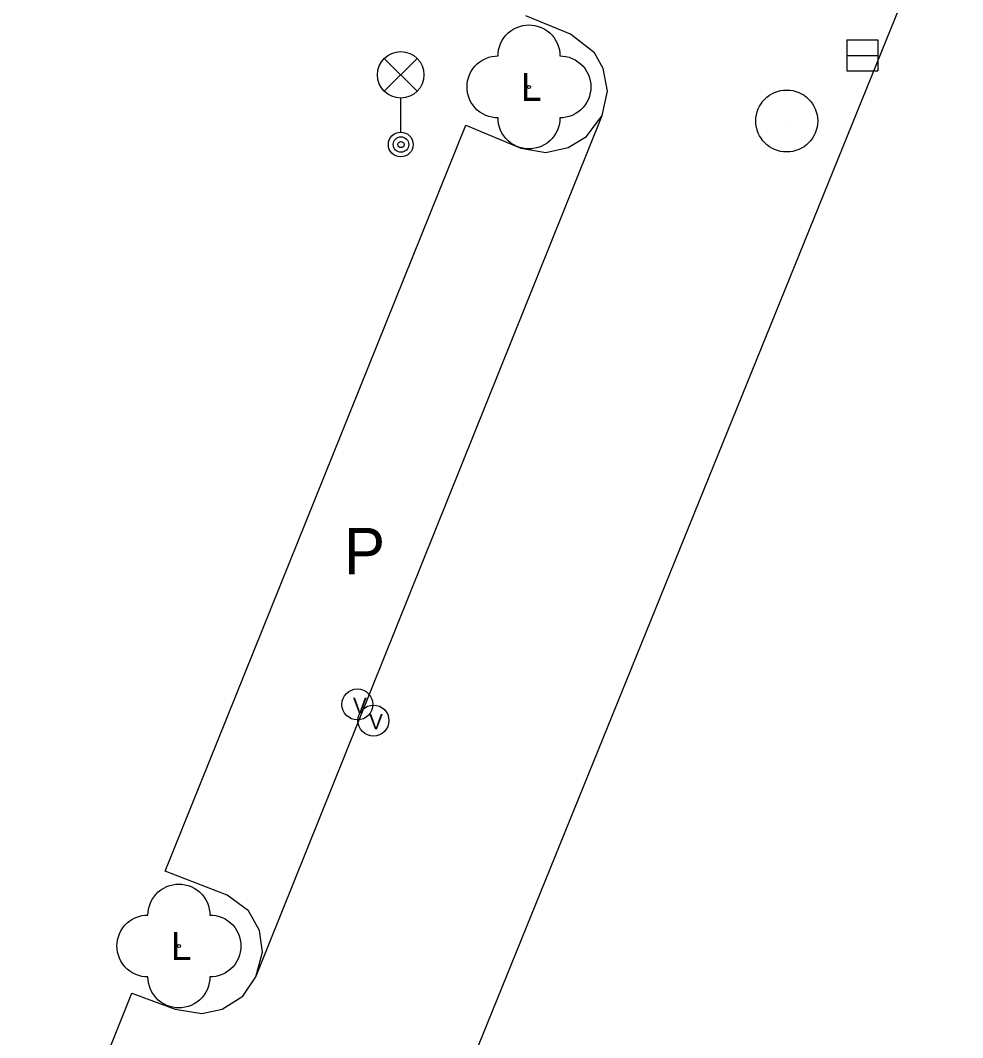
# Model space of a CAD drawing. Extents: x -836568 to -836015, y -1070547 to -1070212.
# Drawn here: x -836346.87 to -836331.66, y -1070399.69 to -1070383.27 of the extents above; entities that cross this region are included whole.
import ezdxf

# ---------------------------------------------------------------- set-up
doc = ezdxf.new("R2010")
doc.units = 0
for name, color, linetype in [('BodPole_mer', 7, 'Continuous'), ('Doprava_hranice', 7, 'Continuous'), ('Doprava_kody', 7, 'Continuous'), ('PovrZnIS_body', 7, 'Continuous'), ('Zelen_body', 7, 'Continuous')]:
    doc.layers.add(name, color=color, linetype=linetype)

msp = doc.modelspace()

# ---------------------------------------------------------------- linework, layer by layer
at = {"layer": 'BodPole_mer'}
for p, q in [((-836337.99, -1070383.49), (-836337.99, -1070383.49)), ((-836337.6, -1070383.79), (-836337.6, -1070383.79)), ((-836333.28, -1070383.83), (-836333.28, -1070383.83)), ((-836337.46, -1070384.04), (-836337.46, -1070384.04)), ((-836338.66, -1070384.34), (-836338.66, -1070384.34)), ((-836337.39, -1070384.41), (-836337.39, -1070384.41)), ((-836337.48, -1070384.8), (-836337.48, -1070384.8)), ((-836334.5, -1070384.89), (-836334.5, -1070384.89)), ((-836339.68, -1070384.96), (-836339.68, -1070384.96)), ((-836337.73, -1070385.14), (-836337.73, -1070385.14)), ((-836340.73, -1070385.27), (-836340.73, -1070385.27)), ((-836338.79, -1070385.33), (-836338.79, -1070385.33)), ((-836338.39, -1070385.4), (-836338.39, -1070385.4)), ((-836338.03, -1070385.32), (-836338.03, -1070385.32)), ((-836341.43, -1070394.31), (-836341.43, -1070394.31)), ((-836341.17, -1070394.57), (-836341.17, -1070394.57)), ((-836344.53, -1070397), (-836344.53, -1070397)), ((-836343.53, -1070397.39), (-836343.53, -1070397.39)), ((-836343.19, -1070397.64), (-836343.19, -1070397.64)), ((-836343.01, -1070397.96), (-836343.01, -1070397.96)), ((-836344.31, -1070398.21), (-836344.31, -1070398.21)), ((-836342.96, -1070398.31), (-836342.96, -1070398.31)), ((-836343.07, -1070398.71), (-836343.07, -1070398.71)), ((-836345.07, -1070398.97), (-836345.07, -1070398.97)), ((-836343.28, -1070399.02), (-836343.28, -1070399.02)), ((-836344.37, -1070399.23), (-836344.37, -1070399.23)), ((-836343.94, -1070399.3), (-836343.94, -1070399.3)), ((-836343.61, -1070399.23), (-836343.61, -1070399.23))]:
    msp.add_line(p, q, dxfattribs=at)
at = {"layer": 'Doprava_hranice'}
msp.add_line((-836343.07, -1070398.71), (-836337.48, -1070384.8), dxfattribs=at)
for points in [[(-836331.66, -1070380.54), (-836339.56, -1070400.02), (-836341.79, -1070405.5), (-836342.16, -1070406.47), (-836342.54, -1070407.49), (-836342.75, -1070408.5), (-836342.67, -1070409.47), (-836342.18, -1070410.44), (-836341.51, -1070411.06), (-836340.95, -1070411.41)], [(-836346.87, -1070403.46), (-836345.07, -1070398.97), (-836344.37, -1070399.23), (-836343.94, -1070399.3), (-836343.61, -1070399.23), (-836343.28, -1070399.02), (-836343.07, -1070398.71), (-836342.96, -1070398.31), (-836343.01, -1070397.96), (-836343.19, -1070397.64), (-836343.53, -1070397.39), (-836344.53, -1070397), (-836339.68, -1070384.96), (-836338.79, -1070385.33), (-836338.39, -1070385.4), (-836338.03, -1070385.32), (-836337.73, -1070385.14), (-836337.48, -1070384.8), (-836337.39, -1070384.41), (-836337.46, -1070384.04), (-836337.6, -1070383.79), (-836337.99, -1070383.49), (-836338.71, -1070383.19)]]:
    msp.add_lwpolyline(points, dxfattribs=at)
at = {"layer": 'PovrZnIS_body'}
for p, q in [((-836333.53, -1070383.58), (-836333.03, -1070383.58)), ((-836333.53, -1070383.58), (-836333.53, -1070384.08)), ((-836333.03, -1070383.58), (-836333.03, -1070384.08)), ((-836340.995, -1070384.41), (-836340.465, -1070383.88)), ((-836340.995, -1070383.88), (-836340.465, -1070384.41)), ((-836333.53, -1070383.83), (-836333.03, -1070383.83)), ((-836333.53, -1070384.08), (-836333.03, -1070384.08)), ((-836340.73, -1070385.07), (-836340.73, -1070384.52))]:
    msp.add_line(p, q, dxfattribs=at)
for centre, radius in [((-836334.5, -1070384.89), 0.5), ((-836341.43, -1070394.31), 0.25), ((-836341.17, -1070394.57), 0.25)]:
    msp.add_circle(centre, radius, dxfattribs=at)
for centre, major_axis in [((-836340.73, -1070384.145), (0.375, 0)), ((-836340.73, -1070385.27), (0.2, 0)), ((-836340.726, -1070385.27), (0.125, 0)), ((-836340.726, -1070385.27), (0.05, 0))]:
    msp.add_ellipse(centre, major_axis=major_axis, ratio=0.999998, dxfattribs=at)
at = {"layer": 'Zelen_body'}
for p, q in [((-836338.66, -1070384.34), (-836338.66, -1070384.34)), ((-836344.31, -1070398.21), (-836344.31, -1070398.21))]:
    msp.add_line(p, q, dxfattribs=at)
for points in [[(-836339.16, -1070383.84), (-836339.158, -1070383.792), (-836339.15, -1070383.743), (-836339.138, -1070383.693), (-836339.12, -1070383.644), (-836339.096, -1070383.595), (-836339.067, -1070383.549), (-836339.033, -1070383.506), (-836338.994, -1070383.467), (-836338.951, -1070383.433), (-836338.905, -1070383.404), (-836338.856, -1070383.38), (-836338.807, -1070383.362), (-836338.757, -1070383.35), (-836338.708, -1070383.342), (-836338.66, -1070383.34), (-836338.612, -1070383.342), (-836338.563, -1070383.35), (-836338.513, -1070383.362), (-836338.464, -1070383.38), (-836338.415, -1070383.404), (-836338.369, -1070383.433), (-836338.326, -1070383.467), (-836338.287, -1070383.506), (-836338.253, -1070383.549), (-836338.224, -1070383.595), (-836338.2, -1070383.644), (-836338.182, -1070383.693), (-836338.17, -1070383.743), (-836338.162, -1070383.792), (-836338.16, -1070383.84)], [(-836339.16, -1070384.84), (-836339.208, -1070384.838), (-836339.257, -1070384.83), (-836339.307, -1070384.818), (-836339.356, -1070384.8), (-836339.405, -1070384.776), (-836339.451, -1070384.747), (-836339.494, -1070384.713), (-836339.533, -1070384.674), (-836339.567, -1070384.631), (-836339.596, -1070384.585), (-836339.62, -1070384.536), (-836339.638, -1070384.487), (-836339.65, -1070384.437), (-836339.658, -1070384.388), (-836339.66, -1070384.34), (-836339.658, -1070384.292), (-836339.65, -1070384.243), (-836339.638, -1070384.193), (-836339.62, -1070384.144), (-836339.596, -1070384.095), (-836339.567, -1070384.049), (-836339.533, -1070384.006), (-836339.494, -1070383.967), (-836339.451, -1070383.933), (-836339.405, -1070383.904), (-836339.356, -1070383.88), (-836339.307, -1070383.862), (-836339.257, -1070383.85), (-836339.208, -1070383.842), (-836339.16, -1070383.84)], [(-836338.16, -1070383.84), (-836338.112, -1070383.842), (-836338.063, -1070383.85), (-836338.013, -1070383.862), (-836337.964, -1070383.88), (-836337.915, -1070383.904), (-836337.869, -1070383.933), (-836337.826, -1070383.967), (-836337.787, -1070384.006), (-836337.753, -1070384.049), (-836337.724, -1070384.095), (-836337.7, -1070384.144), (-836337.682, -1070384.193), (-836337.67, -1070384.243), (-836337.662, -1070384.292), (-836337.66, -1070384.34), (-836337.662, -1070384.388), (-836337.67, -1070384.437), (-836337.682, -1070384.487), (-836337.7, -1070384.536), (-836337.724, -1070384.585), (-836337.753, -1070384.631), (-836337.787, -1070384.674), (-836337.826, -1070384.713), (-836337.869, -1070384.747), (-836337.915, -1070384.776), (-836337.964, -1070384.8), (-836338.013, -1070384.818), (-836338.063, -1070384.83), (-836338.112, -1070384.838), (-836338.16, -1070384.84)], [(-836338.16, -1070384.84), (-836338.162, -1070384.888), (-836338.17, -1070384.937), (-836338.182, -1070384.987), (-836338.2, -1070385.036), (-836338.224, -1070385.085), (-836338.253, -1070385.131), (-836338.287, -1070385.174), (-836338.326, -1070385.213), (-836338.369, -1070385.247), (-836338.415, -1070385.276), (-836338.464, -1070385.3), (-836338.513, -1070385.318), (-836338.563, -1070385.33), (-836338.612, -1070385.338), (-836338.66, -1070385.34), (-836338.708, -1070385.338), (-836338.757, -1070385.33), (-836338.807, -1070385.318), (-836338.856, -1070385.3), (-836338.905, -1070385.276), (-836338.951, -1070385.247), (-836338.994, -1070385.213), (-836339.033, -1070385.174), (-836339.067, -1070385.131), (-836339.096, -1070385.085), (-836339.12, -1070385.036), (-836339.138, -1070384.987), (-836339.15, -1070384.937), (-836339.158, -1070384.888), (-836339.16, -1070384.84)], [(-836344.81, -1070397.71), (-836344.808, -1070397.662), (-836344.8, -1070397.613), (-836344.788, -1070397.563), (-836344.77, -1070397.514), (-836344.746, -1070397.465), (-836344.717, -1070397.419), (-836344.683, -1070397.376), (-836344.644, -1070397.337), (-836344.601, -1070397.303), (-836344.555, -1070397.274), (-836344.506, -1070397.25), (-836344.457, -1070397.232), (-836344.407, -1070397.22), (-836344.358, -1070397.212), (-836344.31, -1070397.21), (-836344.262, -1070397.212), (-836344.213, -1070397.22), (-836344.163, -1070397.232), (-836344.114, -1070397.25), (-836344.065, -1070397.274), (-836344.019, -1070397.303), (-836343.976, -1070397.337), (-836343.937, -1070397.376), (-836343.903, -1070397.419), (-836343.874, -1070397.465), (-836343.85, -1070397.514), (-836343.832, -1070397.563), (-836343.82, -1070397.613), (-836343.812, -1070397.662), (-836343.81, -1070397.71)], [(-836344.81, -1070398.71), (-836344.858, -1070398.708), (-836344.907, -1070398.7), (-836344.957, -1070398.688), (-836345.006, -1070398.67), (-836345.055, -1070398.646), (-836345.101, -1070398.617), (-836345.144, -1070398.583), (-836345.183, -1070398.544), (-836345.217, -1070398.501), (-836345.246, -1070398.455), (-836345.27, -1070398.406), (-836345.288, -1070398.357), (-836345.3, -1070398.307), (-836345.308, -1070398.258), (-836345.31, -1070398.21), (-836345.308, -1070398.162), (-836345.3, -1070398.113), (-836345.288, -1070398.063), (-836345.27, -1070398.014), (-836345.246, -1070397.965), (-836345.217, -1070397.919), (-836345.183, -1070397.876), (-836345.144, -1070397.837), (-836345.101, -1070397.803), (-836345.055, -1070397.774), (-836345.006, -1070397.75), (-836344.957, -1070397.732), (-836344.907, -1070397.72), (-836344.858, -1070397.712), (-836344.81, -1070397.71)], [(-836343.81, -1070397.71), (-836343.762, -1070397.712), (-836343.713, -1070397.72), (-836343.663, -1070397.732), (-836343.614, -1070397.75), (-836343.565, -1070397.774), (-836343.519, -1070397.803), (-836343.476, -1070397.837), (-836343.437, -1070397.876), (-836343.403, -1070397.919), (-836343.374, -1070397.965), (-836343.35, -1070398.014), (-836343.332, -1070398.063), (-836343.32, -1070398.113), (-836343.312, -1070398.162), (-836343.31, -1070398.21), (-836343.312, -1070398.258), (-836343.32, -1070398.307), (-836343.332, -1070398.357), (-836343.35, -1070398.406), (-836343.374, -1070398.455), (-836343.403, -1070398.501), (-836343.437, -1070398.544), (-836343.476, -1070398.583), (-836343.519, -1070398.617), (-836343.565, -1070398.646), (-836343.614, -1070398.67), (-836343.663, -1070398.688), (-836343.713, -1070398.7), (-836343.762, -1070398.708), (-836343.81, -1070398.71)], [(-836343.81, -1070398.71), (-836343.812, -1070398.758), (-836343.82, -1070398.807), (-836343.832, -1070398.857), (-836343.85, -1070398.906), (-836343.874, -1070398.955), (-836343.903, -1070399.001), (-836343.937, -1070399.044), (-836343.976, -1070399.083), (-836344.019, -1070399.117), (-836344.065, -1070399.146), (-836344.114, -1070399.17), (-836344.163, -1070399.188), (-836344.213, -1070399.2), (-836344.262, -1070399.208), (-836344.31, -1070399.21), (-836344.358, -1070399.208), (-836344.407, -1070399.2), (-836344.457, -1070399.188), (-836344.506, -1070399.17), (-836344.555, -1070399.146), (-836344.601, -1070399.117), (-836344.644, -1070399.083), (-836344.683, -1070399.044), (-836344.717, -1070399.001), (-836344.746, -1070398.955), (-836344.77, -1070398.906), (-836344.788, -1070398.857), (-836344.8, -1070398.807), (-836344.808, -1070398.758), (-836344.81, -1070398.71)]]:
    msp.add_lwpolyline(points, dxfattribs=at)
for centre in [(-836338.66, -1070384.34), (-836344.31, -1070398.21)]:
    msp.add_ellipse(centre, major_axis=(0.025, 0), ratio=0.999997, dxfattribs=at)

# ---------------------------------------------------------------- texts
at = {"layer": 'Doprava_kody'}
msp.add_text('P', height=0.75, dxfattribs=at).set_placement((-836341.65, -1070392.21))
at = {"layer": 'PovrZnIS_body'}
for p in [(-836341.501, -1070394.453), (-836341.241, -1070394.713)]:
    msp.add_text('V', height=0.25, dxfattribs=at).set_placement(p)
at = {"layer": 'Zelen_body'}
for p in [(-836338.791, -1070384.565), (-836344.441, -1070398.435)]:
    msp.add_text('L', height=0.45, dxfattribs=at).set_placement(p)

doc.saveas('drawing.dxf')
